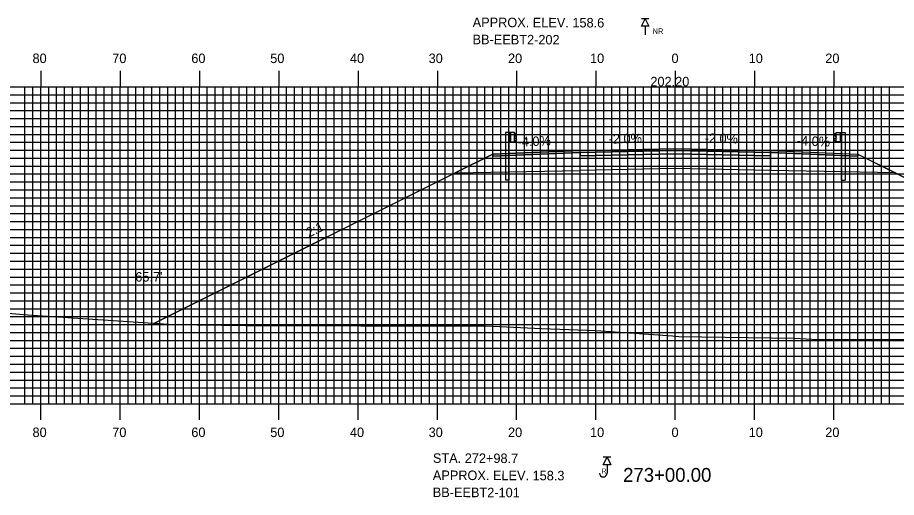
# Model space of a CAD drawing. Extents: x 1809013 to 1809356, y 442591 to 442811.
# Drawn here: x 1809095.4 to 1809206.2, y 442656.9 to 442717.4 of the extents above; entities that cross this region are included whole.
import ezdxf

# ---------------------------------------------------------------- set-up
doc = ezdxf.new("R2010")
doc.units = 0
for name, color, linetype in [('ANNOTATION', 7, 'Continuous'), ('BORING - NO REFUSAL', 7, 'Continuous'), ('BORING - REFUSAL', 7, 'Continuous'), ('D_Guardrail_Beam_Lt', 7, 'Continuous'), ('D_Guardrail_Beam_Rt', 7, 'Continuous'), ('D_Roadway_Centerline', 7, 'Continuous'), ('D_Roadway_Centerline_Text', 7, 'Continuous'), ('D_Roadway_Edge_Shoulder', 7, 'Continuous'), ('D_Roadway_Edge_TW', 7, 'Continuous'), ('D_Roadway_Pavement', 7, 'Continuous'), ('D_Roadway_SlopeLines', 7, 'Continuous'), ('D_Roadway_SubGrade', 7, 'Continuous'), ('D_Text_Standard', 7, 'Continuous'), ('H_V ANNOTATION', 7, 'Continuous'), ('MAJOR', 7, 'Continuous'), ('MINOR', 7, 'Continuous'), ('S_Roadway_Centerline', 7, 'Continuous')]:
    doc.layers.add(name, color=color, linetype=linetype)

msp = doc.modelspace()

# ---------------------------------------------------------------- linework, layer by layer
at = {"layer": 'BORING - NO REFUSAL'}
for p, q in [((1809175, 442717.27), (1809174.04, 442717.27)), ((1809174.52, 442716.31), (1809174.52, 442715.25))]:
    msp.add_line(p, q, dxfattribs=at)
msp.add_lwpolyline([(1809174.52, 442717.27), (1809175, 442716.31), (1809174.04, 442716.31)], close=True, dxfattribs=at)
at = {"layer": 'BORING - REFUSAL'}
for p, q in [((1809170.2, 442661.94), (1809169.24, 442661.94)), ((1809169.72, 442660.98), (1809169.72, 442659.92))]:
    msp.add_line(p, q, dxfattribs=at)
msp.add_lwpolyline([(1809169.72, 442661.94), (1809170.2, 442660.98), (1809169.24, 442660.98)], close=True, dxfattribs=at)
msp.add_arc((1809169.24, 442659.92), 0.485, 180, 0, dxfattribs=at)
at = {"layer": 'D_Guardrail_Beam_Lt'}
for p, q in [((1809156.9, 442702.89), (1809156.9, 442696.89)), ((1809157.37, 442702.89), (1809156.9, 442702.89)), ((1809158.05, 442702.89), (1809157.37, 442702.89)), ((1809157.37, 442702.89), (1809157.37, 442701.73)), ((1809157.43, 442702.89), (1809157.43, 442701.73)), ((1809157.53, 442702.89), (1809157.53, 442701.73)), ((1809158.05, 442701.73), (1809158.05, 442702.89)), ((1809158.05, 442702.81), (1809158.13, 442702.8)), ((1809158.06, 442702.35), (1809158.06, 442702.28)), ((1809158.29, 442702.55), (1809158.09, 442702.41)), ((1809158.09, 442702.21), (1809158.29, 442702.07)), ((1809158.14, 442702.79), (1809158.29, 442702.69)), ((1809157.37, 442701.73), (1809158.05, 442701.73)), ((1809157.39, 442696.89), (1809157.39, 442701.73)), ((1809158.13, 442701.82), (1809158.05, 442701.81)), ((1809158.29, 442701.93), (1809158.14, 442701.83)), ((1809157.39, 442696.89), (1809156.9, 442696.89))]:
    msp.add_line(p, q, dxfattribs=at)
for centre, major_axis, start_param, end_param in [((1809158.14, 442702.35), (-0.0789, 0), 5.323254, 6.283185), ((1809158.14, 442702.28), (-0.0789, 0), 6.283185, 7.243116), ((1809158.12, 442702.75), (0.0417, 0), 0.959931, 1.376053), ((1809158.24, 442702.62), (0.0877, 0), 5.323254, 7.243116), ((1809158.12, 442701.87), (0.0417, 0), 4.907132, 5.323254), ((1809158.24, 442702), (0.0877, 0), 5.323254, 7.243116)]:
    msp.add_ellipse(centre, major_axis=major_axis, ratio=0.995501, start_param=start_param, end_param=end_param, dxfattribs=at)
at = {"layer": 'D_Guardrail_Beam_Rt'}
for p, q in [((1809198.51, 442702.79), (1809198.36, 442702.69)), ((1809198.36, 442702.55), (1809198.56, 442702.41)), ((1809198.56, 442702.21), (1809198.36, 442702.07)), ((1809198.6, 442702.81), (1809198.52, 442702.8)), ((1809198.59, 442702.35), (1809198.59, 442702.28)), ((1809198.6, 442702.89), (1809199.28, 442702.89)), ((1809198.6, 442701.73), (1809198.6, 442702.89)), ((1809199.12, 442702.89), (1809199.12, 442701.73)), ((1809199.22, 442702.89), (1809199.22, 442701.73)), ((1809199.28, 442702.89), (1809199.75, 442702.89)), ((1809199.28, 442702.89), (1809199.28, 442701.73)), ((1809199.75, 442702.89), (1809199.75, 442696.89)), ((1809198.36, 442701.93), (1809198.51, 442701.83)), ((1809198.52, 442701.82), (1809198.6, 442701.81)), ((1809199.28, 442701.73), (1809198.6, 442701.73)), ((1809199.26, 442696.89), (1809199.26, 442701.73)), ((1809199.26, 442696.89), (1809199.75, 442696.89))]:
    msp.add_line(p, q, dxfattribs=at)
for centre, major_axis, start_param, end_param in [((1809198.41, 442702.62), (-0.0877, 0), 5.323254, 7.243116), ((1809198.53, 442702.75), (-0.0417, 0), 4.907132, 5.323254), ((1809198.51, 442702.35), (0.0789, 0), 0, 0.959931), ((1809198.51, 442702.28), (0.0789, 0), 5.323254, 6.283185), ((1809198.41, 442702), (-0.0877, 0), 5.323254, 7.243116), ((1809198.53, 442701.87), (-0.0417, 0), 0.959931, 1.376053)]:
    msp.add_ellipse(centre, major_axis=major_axis, ratio=0.995501, start_param=start_param, end_param=end_param, dxfattribs=at)
at = {"layer": 'D_Roadway_Centerline'}
msp.add_lwpolyline([(1809112.65, 442678.85), (1809150.57, 442697.82), (1809155.32, 442700.19), (1809158.32, 442700.31), (1809166.32, 442700.63), (1809178.32, 442700.87), (1809190.32, 442700.63), (1809198.32, 442700.31), (1809201.32, 442700.19), (1809206.07, 442697.82), (1809247.86, 442676.92)], dxfattribs=at)
at = {"layer": 'D_Roadway_Edge_Shoulder'}
for points in [[(1809166.32, 442700.63), (1809158.32, 442700.31), (1809158.32, 442700.31), (1809155.32, 442700.19), (1809155.32, 442699.94), (1809166.32, 442700.38)], [(1809190.32, 442700.63), (1809198.32, 442700.31), (1809198.32, 442700.31), (1809201.32, 442700.19), (1809201.32, 442699.94), (1809190.32, 442700.38)]]:
    msp.add_lwpolyline(points, close=True, dxfattribs=at)
at = {"layer": 'D_Roadway_Edge_TW'}
msp.add_lwpolyline([(1809166.32, 442700.38), (1809166.32, 442700.63), (1809178.32, 442700.87), (1809190.32, 442700.63), (1809190.32, 442700.38), (1809178.32, 442700.62)], close=True, dxfattribs=at)
at = {"layer": 'D_Roadway_Pavement'}
msp.add_lwpolyline([(1809166.32, 442699.96), (1809166.32, 442700.38), (1809178.32, 442700.62), (1809190.32, 442700.38), (1809190.32, 442699.96), (1809178.32, 442700.2)], close=True, dxfattribs=at)
for points in [[(1809166.32, 442700.38), (1809166.32, 442699.96)], [(1809190.32, 442700.38), (1809190.32, 442699.96)]]:
    msp.add_lwpolyline(points, dxfattribs=at)
at = {"layer": 'D_Roadway_SlopeLines'}
for points in [[(1809155.32, 442700.19), (1809112.65, 442678.85)], [(1809201.32, 442700.19), (1809247.86, 442676.92)]]:
    msp.add_lwpolyline(points, dxfattribs=at)
at = {"layer": 'D_Roadway_SubGrade'}
for points in [[(1809166.32, 442699.96), (1809166.32, 442700.38), (1809155.32, 442699.94), (1809155.32, 442700.19), (1809150.57, 442697.82), (1809166.32, 442698.13)], [(1809166.32, 442698.13), (1809166.32, 442700.38), (1809166.32, 442699.96), (1809178.32, 442700.2), (1809190.32, 442699.96), (1809190.32, 442700.38), (1809190.32, 442698.13), (1809178.32, 442698.37)], [(1809190.32, 442699.96), (1809190.32, 442700.38), (1809201.32, 442699.94), (1809201.32, 442700.19), (1809206.07, 442697.82), (1809190.32, 442698.13)]]:
    msp.add_lwpolyline(points, close=True, dxfattribs=at)
at = {"layer": 'MAJOR'}
for p, q in [((1809098.32, 442710.67), (1809098.32, 442708.67)), ((1809108.32, 442710.67), (1809108.32, 442708.67)), ((1809118.32, 442710.67), (1809118.32, 442708.67)), ((1809128.32, 442710.67), (1809128.32, 442708.67)), ((1809138.32, 442710.67), (1809138.32, 442708.67)), ((1809148.32, 442710.67), (1809148.32, 442708.67)), ((1809158.32, 442710.67), (1809158.32, 442708.67)), ((1809168.32, 442710.67), (1809168.32, 442708.67)), ((1809178.32, 442710.67), (1809178.32, 442708.67)), ((1809188.32, 442710.67), (1809188.32, 442708.67)), ((1809198.32, 442710.67), (1809198.32, 442708.67)), ((1809038.32, 442708.67), (1809318.32, 442708.67)), ((1809038.32, 442708.67), (1809318.32, 442708.67)), ((1809098.32, 442668.67), (1809098.32, 442708.67)), ((1809108.32, 442668.67), (1809108.32, 442708.67)), ((1809118.32, 442668.67), (1809118.32, 442708.67)), ((1809128.32, 442668.67), (1809128.32, 442708.67)), ((1809138.32, 442668.67), (1809138.32, 442708.67)), ((1809148.32, 442668.67), (1809148.32, 442708.67)), ((1809158.32, 442668.67), (1809158.32, 442708.67)), ((1809168.32, 442668.67), (1809168.32, 442708.67)), ((1809178.32, 442668.67), (1809178.32, 442708.67)), ((1809188.32, 442668.67), (1809188.32, 442708.67)), ((1809198.32, 442668.67), (1809198.32, 442708.67)), ((1809038.32, 442703.67), (1809318.32, 442703.67)), ((1809038.32, 442698.67), (1809318.32, 442698.67)), ((1809038.32, 442693.67), (1809318.32, 442693.67)), ((1809038.32, 442688.67), (1809318.32, 442688.67)), ((1809038.32, 442683.67), (1809318.32, 442683.67)), ((1809038.32, 442678.67), (1809318.32, 442678.67)), ((1809038.32, 442673.67), (1809318.32, 442673.67)), ((1809038.32, 442668.67), (1809318.32, 442668.67)), ((1809038.32, 442668.67), (1809318.32, 442668.67)), ((1809098.32, 442666.66), (1809098.32, 442668.67)), ((1809108.32, 442666.66), (1809108.32, 442668.67)), ((1809118.32, 442666.66), (1809118.32, 442668.67)), ((1809128.32, 442666.66), (1809128.32, 442668.67)), ((1809138.32, 442666.66), (1809138.32, 442668.67)), ((1809148.32, 442666.66), (1809148.32, 442668.67)), ((1809158.32, 442666.66), (1809158.32, 442668.67)), ((1809168.32, 442666.66), (1809168.32, 442668.67)), ((1809178.32, 442666.66), (1809178.32, 442668.67)), ((1809188.32, 442666.66), (1809188.32, 442668.67)), ((1809198.32, 442666.66), (1809198.32, 442668.67))]:
    msp.add_line(p, q, dxfattribs=at)
at = {"layer": 'MINOR'}
for p, q in [((1809096.32, 442668.67), (1809096.32, 442708.67)), ((1809097.32, 442668.67), (1809097.32, 442708.67)), ((1809099.32, 442668.67), (1809099.32, 442708.67)), ((1809100.32, 442668.67), (1809100.32, 442708.67)), ((1809101.32, 442668.67), (1809101.32, 442708.67)), ((1809102.32, 442668.67), (1809102.32, 442708.67)), ((1809103.32, 442668.67), (1809103.32, 442708.67)), ((1809104.32, 442668.67), (1809104.32, 442708.67)), ((1809105.32, 442668.67), (1809105.32, 442708.67)), ((1809106.32, 442668.67), (1809106.32, 442708.67)), ((1809107.32, 442668.67), (1809107.32, 442708.67)), ((1809109.32, 442668.67), (1809109.32, 442708.67)), ((1809110.32, 442668.67), (1809110.32, 442708.67)), ((1809111.32, 442668.67), (1809111.32, 442708.67)), ((1809112.32, 442668.67), (1809112.32, 442708.67)), ((1809113.32, 442668.67), (1809113.32, 442708.67)), ((1809114.32, 442668.67), (1809114.32, 442708.67)), ((1809115.32, 442668.67), (1809115.32, 442708.67)), ((1809116.32, 442668.67), (1809116.32, 442708.67)), ((1809117.32, 442668.67), (1809117.32, 442708.67)), ((1809119.32, 442668.67), (1809119.32, 442708.67)), ((1809120.32, 442668.67), (1809120.32, 442708.67)), ((1809121.32, 442668.67), (1809121.32, 442708.67)), ((1809122.32, 442668.67), (1809122.32, 442708.67)), ((1809123.32, 442668.67), (1809123.32, 442708.67)), ((1809124.32, 442668.67), (1809124.32, 442708.67)), ((1809125.32, 442668.67), (1809125.32, 442708.67)), ((1809126.32, 442668.67), (1809126.32, 442708.67)), ((1809127.32, 442668.67), (1809127.32, 442708.67)), ((1809129.32, 442668.67), (1809129.32, 442708.67)), ((1809130.32, 442668.67), (1809130.32, 442708.67)), ((1809131.32, 442668.67), (1809131.32, 442708.67)), ((1809132.32, 442668.67), (1809132.32, 442708.67)), ((1809133.32, 442668.67), (1809133.32, 442708.67)), ((1809134.32, 442668.67), (1809134.32, 442708.67)), ((1809135.32, 442668.67), (1809135.32, 442708.67)), ((1809136.32, 442668.67), (1809136.32, 442708.67)), ((1809137.32, 442668.67), (1809137.32, 442708.67)), ((1809139.32, 442668.67), (1809139.32, 442708.67)), ((1809140.32, 442668.67), (1809140.32, 442708.67)), ((1809141.32, 442668.67), (1809141.32, 442708.67)), ((1809142.32, 442668.67), (1809142.32, 442708.67)), ((1809143.32, 442668.67), (1809143.32, 442708.67)), ((1809144.32, 442668.67), (1809144.32, 442708.67)), ((1809145.32, 442668.67), (1809145.32, 442708.67)), ((1809146.32, 442668.67), (1809146.32, 442708.67)), ((1809147.32, 442668.67), (1809147.32, 442708.67)), ((1809149.32, 442668.67), (1809149.32, 442708.67)), ((1809150.32, 442668.67), (1809150.32, 442708.67)), ((1809151.32, 442668.67), (1809151.32, 442708.67)), ((1809152.32, 442668.67), (1809152.32, 442708.67)), ((1809153.32, 442668.67), (1809153.32, 442708.67)), ((1809154.32, 442668.67), (1809154.32, 442708.67)), ((1809155.32, 442668.67), (1809155.32, 442708.67)), ((1809156.32, 442668.67), (1809156.32, 442708.67)), ((1809157.32, 442668.67), (1809157.32, 442708.67)), ((1809159.32, 442668.67), (1809159.32, 442708.67)), ((1809160.32, 442668.67), (1809160.32, 442708.67)), ((1809161.32, 442668.67), (1809161.32, 442708.67)), ((1809162.32, 442668.67), (1809162.32, 442708.67)), ((1809163.32, 442668.67), (1809163.32, 442708.67)), ((1809164.32, 442668.67), (1809164.32, 442708.67)), ((1809165.32, 442668.67), (1809165.32, 442708.67)), ((1809166.32, 442668.67), (1809166.32, 442708.67)), ((1809167.32, 442668.67), (1809167.32, 442708.67)), ((1809169.32, 442668.67), (1809169.32, 442708.67)), ((1809170.32, 442668.67), (1809170.32, 442708.67)), ((1809171.32, 442668.67), (1809171.32, 442708.67)), ((1809172.32, 442668.67), (1809172.32, 442708.67)), ((1809173.32, 442668.67), (1809173.32, 442708.67)), ((1809174.32, 442668.67), (1809174.32, 442708.67)), ((1809175.32, 442668.67), (1809175.32, 442708.67)), ((1809176.32, 442668.67), (1809176.32, 442708.67)), ((1809177.32, 442668.67), (1809177.32, 442708.67)), ((1809179.32, 442668.67), (1809179.32, 442708.67)), ((1809180.32, 442668.67), (1809180.32, 442708.67)), ((1809181.32, 442668.67), (1809181.32, 442708.67)), ((1809182.32, 442668.67), (1809182.32, 442708.67)), ((1809183.32, 442668.67), (1809183.32, 442708.67)), ((1809184.32, 442668.67), (1809184.32, 442708.67)), ((1809185.32, 442668.67), (1809185.32, 442708.67)), ((1809186.32, 442668.67), (1809186.32, 442708.67)), ((1809187.32, 442668.67), (1809187.32, 442708.67)), ((1809189.32, 442668.67), (1809189.32, 442708.67)), ((1809190.32, 442668.67), (1809190.32, 442708.67)), ((1809191.32, 442668.67), (1809191.32, 442708.67)), ((1809192.32, 442668.67), (1809192.32, 442708.67)), ((1809193.32, 442668.67), (1809193.32, 442708.67)), ((1809194.32, 442668.67), (1809194.32, 442708.67)), ((1809195.32, 442668.67), (1809195.32, 442708.67)), ((1809196.32, 442668.67), (1809196.32, 442708.67)), ((1809197.32, 442668.67), (1809197.32, 442708.67)), ((1809199.32, 442668.67), (1809199.32, 442708.67)), ((1809200.32, 442668.67), (1809200.32, 442708.67)), ((1809201.32, 442668.67), (1809201.32, 442708.67)), ((1809202.32, 442668.67), (1809202.32, 442708.67)), ((1809203.32, 442668.67), (1809203.32, 442708.67)), ((1809204.32, 442668.67), (1809204.32, 442708.67)), ((1809205.32, 442668.67), (1809205.32, 442708.67)), ((1809038.32, 442707.67), (1809318.32, 442707.67)), ((1809038.32, 442706.67), (1809318.32, 442706.67)), ((1809038.32, 442705.67), (1809318.32, 442705.67)), ((1809038.32, 442704.67), (1809318.32, 442704.67)), ((1809038.32, 442702.67), (1809318.32, 442702.67)), ((1809038.32, 442701.67), (1809318.32, 442701.67)), ((1809038.32, 442700.67), (1809318.32, 442700.67)), ((1809038.32, 442699.67), (1809318.32, 442699.67)), ((1809038.32, 442697.67), (1809318.32, 442697.67)), ((1809038.32, 442696.67), (1809318.32, 442696.67)), ((1809038.32, 442695.67), (1809318.32, 442695.67)), ((1809038.32, 442694.67), (1809318.32, 442694.67)), ((1809038.32, 442692.67), (1809318.32, 442692.67)), ((1809038.32, 442691.67), (1809318.32, 442691.67)), ((1809038.32, 442690.67), (1809318.32, 442690.67)), ((1809038.32, 442689.67), (1809318.32, 442689.67)), ((1809038.32, 442687.67), (1809318.32, 442687.67)), ((1809038.32, 442686.67), (1809318.32, 442686.67)), ((1809038.32, 442685.67), (1809318.32, 442685.67)), ((1809038.32, 442684.67), (1809318.32, 442684.67)), ((1809038.32, 442682.67), (1809318.32, 442682.67)), ((1809038.32, 442681.67), (1809318.32, 442681.67)), ((1809038.32, 442680.67), (1809318.32, 442680.67)), ((1809038.32, 442679.67), (1809318.32, 442679.67)), ((1809038.32, 442677.67), (1809318.32, 442677.67)), ((1809038.32, 442676.67), (1809318.32, 442676.67)), ((1809038.32, 442675.67), (1809318.32, 442675.67)), ((1809038.32, 442674.67), (1809318.32, 442674.67)), ((1809038.32, 442672.67), (1809318.32, 442672.67)), ((1809038.32, 442671.67), (1809318.32, 442671.67)), ((1809038.32, 442670.67), (1809318.32, 442670.67)), ((1809038.32, 442669.67), (1809318.32, 442669.67))]:
    msp.add_line(p, q, dxfattribs=at)
at = {"layer": 'S_Roadway_Centerline'}
msp.add_lwpolyline([(1809093.17, 442680.19), (1809096.65, 442679.9), (1809115.04, 442678.69), (1809124.14, 442678.56), (1809138.68, 442678.51), (1809151.4, 442678.52), (1809154.39, 442678.52), (1809161.44, 442678.19), (1809168.33, 442677.9), (1809177.97, 442677.23), (1809178.39, 442677.21), (1809178.77, 442677.18), (1809193.37, 442676.95), (1809196.27, 442676.78), (1809204.17, 442676.77), (1809205.13, 442676.77), (1809205.65, 442676.78), (1809207.67, 442676.78)], dxfattribs=at)

# ---------------------------------------------------------------- texts
at = {"layer": 'ANNOTATION'}
for s, rotation, p in [('-4.0%', 2.2906, (1809158.46, 442701.12)), ('-2.0%', 1.1458, (1809169.93, 442701.5)), ('-2.0%', 358.8542, (1809182.01, 442701.6)), ('-4.0%', 357.7094, (1809193.62, 442701.3)), ('2:1', 26.5651, (1809132.13, 442689.63))]:
    msp.add_text(s, height=1.2, rotation=rotation, dxfattribs=at).set_placement(p)
at = {"layer": 'BORING - NO REFUSAL'}
for s, p in [('APPROX. ELEV. 158.6', (1809152.77, 442716.21)), ('BB-EEBT2-202', (1809152.76, 442714.05))]:
    msp.add_text(s, height=1.2, rotation=359.8142, dxfattribs=at).set_placement(p)
msp.add_text('NR', height=0.7, dxfattribs=at).set_placement((1809175.46, 442715.35))
at = {"layer": 'BORING - REFUSAL'}
for s, p in [('STA. 272+98.7', (1809147.76, 442661.22)), ('APPROX. ELEV. 158.3', (1809147.75, 442659.06)), ('BB-EEBT2-101', (1809147.74, 442656.9))]:
    msp.add_text(s, height=1.2, rotation=359.8142, dxfattribs=at).set_placement(p)
msp.add_text('R', height=0.64, dxfattribs=at).set_placement((1809169.02, 442659.86))
at = {"layer": 'D_Roadway_Centerline'}
for s, p in [('C', (1809178.32, 442700.87)), ('L', (1809178.32, 442700.86))]:
    msp.add_text(s, height=0.0146, dxfattribs=at).set_placement(p)
at = {"layer": 'D_Roadway_Centerline_Text'}
msp.add_text('202.20', height=1.2, dxfattribs=at).set_placement((1809175.18, 442708.73))
at = {"layer": 'D_Text_Standard'}
msp.add_text("65.7'", height=1.2, dxfattribs=at).set_placement((1809110.24, 442684.09))
at = {"layer": 'H_V ANNOTATION'}
for s, height, p in [('80', 1.2, (1809097.28, 442711.67)), ('70', 1.2, (1809107.33, 442711.67)), ('60', 1.2, (1809117.3, 442711.67)), ('50', 1.2, (1809127.25, 442711.67)), ('40', 1.2, (1809137.3, 442711.67)), ('30', 1.2, (1809147.22, 442711.67)), ('20', 1.2, (1809157.23, 442711.67)), ('10', 1.2, (1809167.57, 442711.67)), ('0', 1.2, (1809177.84, 442711.67)), ('10', 1.2, (1809187.57, 442711.67)), ('20', 1.2, (1809197.23, 442711.67)), ('80', 1.2, (1809097.28, 442664.47)), ('70', 1.2, (1809107.33, 442664.47)), ('60', 1.2, (1809117.3, 442664.47)), ('50', 1.2, (1809127.25, 442664.47)), ('40', 1.2, (1809137.3, 442664.47)), ('30', 1.2, (1809147.22, 442664.47)), ('20', 1.2, (1809157.23, 442664.47)), ('10', 1.2, (1809167.57, 442664.47)), ('0', 1.2, (1809177.84, 442664.47)), ('10', 1.2, (1809187.57, 442664.47)), ('20', 1.2, (1809197.23, 442664.47)), ('273+00.00', 1.75, (1809171.74, 442658.82))]:
    msp.add_text(s, height=height, dxfattribs=at).set_placement(p)

doc.saveas('drawing.dxf')
